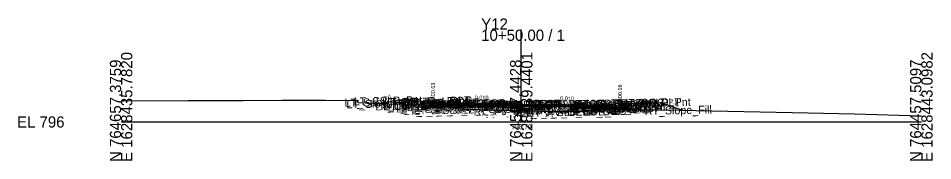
# Model space of a CAD drawing. Extents: x -26 to 203, y -10 to 3521.
# Drawn here: x -25.7 to 202.8, y 990.3 to 1025.9 of the extents above; entities that cross this region are included whole.
import ezdxf

# ---------------------------------------------------------------- set-up
doc = ezdxf.new("R2010")
doc.units = 0
for name, color, linetype in [('Default', 7, 'Continuous'), ('Exist CMT Pavement', 7, 'Continuous'), ('Exist Cross Section Cell', 7, 'Continuous'), ('Exist XS Center Line Elevation Label', 7, 'Continuous'), ('Exist XS Ground Line', 7, 'Continuous'), ('Prop CMT Conc Surface', 7, 'Continuous'), ('Prop CMT Concrete Structures', 7, 'Continuous'), ('Prop CMT Pvmt Course 1', 7, 'Continuous'), ('Prop CMT Pvmt Course 1 CG', 7, 'Continuous'), ('Prop CMT Pvmt Course 1 Wedge', 7, 'Continuous'), ('Prop CMT Pvmt Course 2', 7, 'Continuous'), ('Prop CMT Pvmt Course 2 Wedge', 7, 'Continuous'), ('Prop CMT Pvmt Course 3', 7, 'Continuous'), ('Prop CMT Pvmt Course 3 Wedge', 7, 'Continuous'), ('Prop CMT Pvmt Surface', 7, 'Continuous'), ('Prop CMT Pvmt Wedge Surface 1', 7, 'Continuous'), ('Prop CMT Pvmt Wedge Surface 2', 7, 'Continuous'), ('Prop CMT Pvmt Wedge Surface 3', 7, 'Continuous'), ('Prop CMT Slope Grass', 7, 'Continuous'), ('Prop CMT Subgrade Earthwork', 7, 'Continuous'), ('Prop XS Hydro Elevations', 7, 'Continuous'), ('Prop XS SE Text', 7, 'Continuous'), ('Prop XS Side Slope Text', 7, 'Continuous'), ('Scratch_Level_0', 7, 'Continuous')]:
    doc.layers.add(name, color=color, linetype=linetype)

msp = doc.modelspace()

# ---------------------------------------------------------------- linework, layer by layer
at = {"layer": 'Exist CMT Pavement'}
for points in [[(100, 1002.79), (97.69, 1002.83), (85.63, 1003.08)], [(85.63, 1003.08), (85.63, 1003.08)], [(100, 1002.79), (113.86, 1002.55)], [(113.86, 1002.55), (113.86, 1002.55)]]:
    msp.add_lwpolyline(points, dxfattribs=at)
at = {"layer": 'Exist Cross Section Cell'}
for p, q in [((100, 1000), (100, 1023.09)), ((0, 1000), (100, 1000)), ((100, 1000), (200, 1000))]:
    msp.add_line(p, q, dxfattribs=at)
at = {"layer": 'Exist XS Ground Line'}
msp.add_lwpolyline([(0, 1005.28), (0.59, 1005.28), (16.74, 1005.4), (30.48, 1005.4), (40.27, 1005.47), (51.02, 1005.49), (58.8, 1005.41), (59.21, 1004.91), (66.95, 1004.55), (70.07, 1004.41), (74.01, 1004.03), (80.92, 1003.88), (85.63, 1003.08), (97.69, 1002.83), (100, 1002.79), (113.86, 1002.55), (116.68, 1002.85), (119.9, 1003.29), (122.33, 1003.21), (139.66, 1002.98), (171.73, 1002.25), (183.27, 1002.03), (200, 1001.5)], dxfattribs=at)
at = {"layer": 'Prop CMT Conc Surface'}
for points in [[(77.97, 1004.63), (77.97, 1005.13), (77.47, 1005.13)], [(79.97, 1004.69), (77.97, 1004.63)], [(122.69, 1004.26), (124.69, 1004.16)], [(124.69, 1004.16), (124.69, 1004.66), (125.19, 1004.66)]]:
    msp.add_lwpolyline(points, dxfattribs=at)
at = {"layer": 'Prop CMT Concrete Structures'}
for points in [[(79.97, 1004.69), (77.97, 1004.63), (77.97, 1005.13), (77.47, 1005.13)], [(77.47, 1005.13), (77.47, 1004.13), (79.97, 1004.11)], [(79.97, 1004.11), (79.97, 1004.69)], [(122.69, 1004.26), (124.69, 1004.16), (124.69, 1004.66), (125.19, 1004.66)], [(125.19, 1004.66), (125.19, 1003.66), (122.69, 1003.68)], [(122.69, 1003.68), (122.69, 1004.26)]]:
    msp.add_lwpolyline(points, dxfattribs=at)
at = {"layer": 'Prop CMT Pvmt Course 1'}
for points in [[(100, 1004.49), (79.97, 1004.69)], [(79.97, 1004.69), (79.97, 1004.44)], [(79.97, 1004.44), (85.63, 1004.39)], [(85.63, 1004.39), (85.63, 1004.51)], [(85.63, 1004.51), (100, 1004.37)], [(100, 1004.24), (100, 1004.49)], [(100, 1004.49), (122.69, 1004.26)], [(100, 1004.24), (100, 1004.49)], [(100, 1004.37), (100, 1004.24), (100, 1004.24)], [(113.86, 1004.23), (100, 1004.37)], [(100, 1004.37), (100, 1004.24), (100, 1004.24)], [(113.86, 1004.1), (113.86, 1004.23)], [(122.69, 1004.01), (113.86, 1004.1)], [(122.69, 1004.26), (122.69, 1004.01)]]:
    msp.add_lwpolyline(points, dxfattribs=at)
at = {"layer": 'Prop CMT Pvmt Course 1 CG'}
for points in [[(79.97, 1004.11), (76.97, 1004.14), (76.64, 1003.81)], [(76.64, 1003.81), (79.97, 1003.78)], [(79.97, 1003.78), (79.97, 1004.11)], [(122.69, 1003.68), (125.69, 1003.65), (126.03, 1003.31)], [(122.69, 1003.35), (122.69, 1003.68)], [(126.03, 1003.31), (122.69, 1003.35)]]:
    msp.add_lwpolyline(points, dxfattribs=at)
at = {"layer": 'Prop CMT Pvmt Course 1 Wedge'}
for points in [[(85.63, 1004.51), (85.63, 1004.51)], [(85.63, 1004.51), (97.69, 1004.39), (100, 1004.37)], [(85.63, 1004.39), (85.63, 1004.51)], [(100, 1004.24), (97.69, 1004.26), (85.63, 1004.39)], [(85.63, 1004.39), (85.63, 1004.39)], [(100, 1004.37), (100, 1004.24)], [(100, 1004.37), (113.86, 1004.23)], [(100, 1004.24), (100, 1004.37)], [(113.86, 1004.1), (100, 1004.24)], [(113.86, 1004.23), (113.86, 1004.1), (113.86, 1004.1)]]:
    msp.add_lwpolyline(points, dxfattribs=at)
at = {"layer": 'Prop CMT Pvmt Course 2'}
for points in [[(85.63, 1004.39), (79.97, 1004.44)], [(79.97, 1004.44), (79.97, 1004.11)], [(79.97, 1004.11), (85.63, 1004.05)], [(85.63, 1004.05), (85.63, 1004.39)], [(113.86, 1003.77), (113.86, 1004.1)], [(113.86, 1004.1), (122.69, 1004.01)], [(122.69, 1003.68), (113.86, 1003.77)], [(122.69, 1004.01), (122.69, 1003.68)]]:
    msp.add_lwpolyline(points, dxfattribs=at)
at = {"layer": 'Prop CMT Pvmt Course 2 Wedge'}
for points in [[(85.63, 1004.39), (85.63, 1004.39)], [(85.63, 1004.39), (97.69, 1004.26), (100, 1004.24)], [(85.63, 1004.05), (85.63, 1004.39)], [(100, 1003.91), (97.69, 1003.93), (85.63, 1004.05)], [(85.63, 1004.05), (85.63, 1004.05)], [(100, 1004.24), (100, 1003.91)], [(100, 1004.24), (113.86, 1004.1)], [(100, 1003.91), (100, 1004.24)], [(113.86, 1003.77), (100, 1003.91)], [(113.86, 1004.1), (113.86, 1003.77), (113.86, 1003.77)]]:
    msp.add_lwpolyline(points, dxfattribs=at)
at = {"layer": 'Prop CMT Pvmt Course 3'}
for points in [[(85.63, 1004.05), (79.97, 1004.11)], [(79.97, 1004.11), (79.97, 1003.78)], [(79.97, 1003.78), (85.63, 1003.72)], [(85.63, 1003.72), (85.63, 1004.05)], [(113.86, 1003.77), (122.69, 1003.68)], [(113.86, 1003.44), (113.86, 1003.77)], [(122.69, 1003.35), (113.86, 1003.44)], [(122.69, 1003.68), (122.69, 1003.35)]]:
    msp.add_lwpolyline(points, dxfattribs=at)
at = {"layer": 'Prop CMT Pvmt Course 3 Wedge'}
for points in [[(85.63, 1004.05), (85.63, 1004.05)], [(85.63, 1004.05), (97.69, 1003.93), (100, 1003.91)], [(85.63, 1003.08), (85.63, 1004.05)], [(100, 1003.91), (100, 1002.79)], [(100, 1003.91), (113.86, 1003.77)], [(100, 1002.79), (100, 1003.91)], [(113.86, 1003.77), (113.86, 1002.55), (113.86, 1002.55)], [(100, 1002.79), (97.69, 1002.83), (85.63, 1003.08)], [(85.63, 1003.08), (85.63, 1003.08)], [(113.86, 1002.55), (100, 1002.79)]]:
    msp.add_lwpolyline(points, dxfattribs=at)
at = {"layer": 'Prop CMT Pvmt Surface'}
for points in [[(100, 1004.49), (79.97, 1004.69)], [(100, 1004.49), (122.69, 1004.26)]]:
    msp.add_lwpolyline(points, dxfattribs=at)
at = {"layer": 'Prop CMT Pvmt Wedge Surface 1'}
for points in [[(79.97, 1004.44), (79.97, 1004.69)], [(85.63, 1004.39), (79.97, 1004.44)], [(100, 1004.37), (85.63, 1004.51)], [(85.63, 1004.51), (85.63, 1004.39)], [(100, 1004.37), (113.86, 1004.23)], [(113.86, 1004.23), (113.86, 1004.1)], [(113.86, 1004.1), (122.69, 1004.01)], [(122.69, 1004.01), (122.69, 1004.26)]]:
    msp.add_lwpolyline(points, dxfattribs=at)
at = {"layer": 'Prop CMT Pvmt Wedge Surface 2'}
for points in [[(79.97, 1004.44), (79.97, 1004.69)], [(100, 1004.24), (79.97, 1004.44)], [(100, 1004.24), (122.69, 1004.01)], [(122.69, 1004.01), (122.69, 1004.26)]]:
    msp.add_lwpolyline(points, dxfattribs=at)
at = {"layer": 'Prop CMT Pvmt Wedge Surface 3'}
for points in [[(79.97, 1004.11), (79.97, 1004.69)], [(100, 1003.91), (79.97, 1004.11)], [(100, 1003.91), (122.69, 1003.68)], [(122.69, 1003.68), (122.69, 1004.26)]]:
    msp.add_lwpolyline(points, dxfattribs=at)
at = {"layer": 'Prop CMT Slope Grass'}
for points in [[(77.47, 1005.13), (67.97, 1005.32), (65.82, 1004.6)], [(125.19, 1004.66), (134.69, 1004.85), (140.37, 1002.96)]]:
    msp.add_lwpolyline(points, dxfattribs=at)
at = {"layer": 'Prop CMT Subgrade Earthwork'}
for points in [[(79.97, 1003.78), (76.64, 1003.81), (75.28, 1005.18)], [(85.63, 1003.72), (79.97, 1003.78)], [(85.63, 1003.72), (85.65, 1003.08)], [(113.86, 1003.44), (113.84, 1002.55)], [(113.86, 1003.44), (122.69, 1003.35)], [(122.69, 1003.35), (126.03, 1003.31), (127.42, 1004.71)]]:
    msp.add_lwpolyline(points, dxfattribs=at)

# ---------------------------------------------------------------- texts
at = {"layer": 'Default'}
msp.add_text('-', height=0.0001, dxfattribs=at).set_placement((0, 1000))
at = {"layer": 'Exist Cross Section Cell'}
for s, p in [('Y12', (90, 1023.09)), ('10+50.00 / 1', (90, 1020.29)), ('EL 796', (-26, 998.6))]:
    msp.add_text(s, height=2.8, dxfattribs=at).set_placement(p)
for s, p in [('E 1628435.7820', (2.8, 990)), ('E 1628439.4401', (102.8, 990)), ('E 1628443.0982', (202.8, 990)), ('N 764657.3759', (0, 990)), ('N 764557.4428', (100, 990)), ('N 764457.5097', (200, 990))]:
    msp.add_text(s, height=2.8, rotation=90, dxfattribs=at).set_placement(p)
at = {"layer": 'Exist XS Center Line Elevation Label'}
msp.add_text('798.79', height=1.2, dxfattribs=at).set_placement((97.54, 998.19))
at = {"layer": 'Prop XS Hydro Elevations'}
for s, p in [('800.63', (78.47, 1005.63)), ('800.16', (125.19, 1005.16))]:
    msp.add_text(s, height=1, rotation=90, dxfattribs=at).set_placement(p)
at = {"layer": 'Prop XS SE Text'}
for p in [(88.37, 1005.61), (109.73, 1005.39)]:
    msp.add_text('0.010', height=1, rotation=359.4271, dxfattribs=at).set_placement(p)
at = {"layer": 'Prop XS Side Slope Text'}
for rotation, p in [(18.4332, (65.91, 1005.42)), (341.5668, (137.02, 1004.87))]:
    msp.add_text('3:1', height=1, rotation=rotation, dxfattribs=at).set_placement(p)
at = {"layer": 'Scratch_Level_0'}
for s, p in [('LT_Sub_Trench_Out_DLT', (55.87, 1003.79)), ('LT_Slope_Fill', (56.36, 1003.41)), ('LT_CSLP_Pnt', (58.17, 1004.13)), ('LT_CG_Top_Face', (65.25, 1003.88)), ('LT_CG_Top_BOC', (65.78, 1003.9)), ('LT_CG_Top_Gut', (66.23, 1003.4)), ('LT_PV2_OEOT', (70.17, 1003.25)), ('LT_PV1_OEOT', (70.74, 1003.51)), ('LT_PV2_OEEOP', (74.96, 1003.17)), ('LT_PV1_OEEOP', (75.53, 1003.31)), ('RT_PV1_IEEOP', (90.49, 1003.18)), ('LT_PV1_IEEOP', (90.54, 1003.18)), ('PV1_PGL', (94.49, 1003.38)), ('RT_Sub_Trench_Out_DLT', (107.97, 1003.32)), ('RT_CG_Top_Face', (111.93, 1003.41)), ('RT_CG_Top_BOC', (113.45, 1003.43)), ('RT_CSLP_Pnt', (124.84, 1003.66)), ('LT_CG1_Shelf_Out', (63.55, 1002.87)), ('LT_CG_Bot_BOC', (65.81, 1002.9)), ('LT_Sub_OEOP', (66.78, 1002.61)), ('LT_CG_Bot_IE', (69.91, 1002.91)), ('LT_Sub_OEOT', (70.07, 1002.58)), ('LT_PV3_OEOT', (70.17, 1002.91)), ('LT_PV_Sub_Tie_Out', (70.61, 1001.77)), ('LT_PV_OEEOP_EG', (73.2, 1001.83)), ('LT_Sub_OEEOP', (74.87, 1002.5)), ('LT_PV3_OEEOP', (74.96, 1002.84)), ('RT_PV_IEEOP_EG', (88.16, 1001.55)), ('LT_PV_IEEOP_EG', (88.21, 1001.55)), ('RT_PV2_IEEOP', (89.93, 1003.04)), ('RT_PV3_IEEOP', (89.93, 1002.71)), ('LT_PV2_IEEOP', (89.97, 1003.04)), ('LT_PV3_IEEOP', (89.97, 1002.71)), ('PV2_PGL', (93.93, 1003.12)), ('RT_PV_Sub_Tie_Out', (98.76, 1001.25)), ('RT_PV_OEEOP_EG', (101.37, 1001.3)), ('RT_Sub_OEEOP', (103.04, 1002.22)), ('RT_PV2_OEEOP', (103.14, 1002.89)), ('RT_PV3_OEEOP', (103.14, 1002.56)), ('RT_PV1_OEEOP', (103.7, 1003.02)), ('RT_CG1_Shelf_Out', (112.22, 1002.38)), ('RT_CG_Bot_IE', (112.58, 1002.48)), ('RT_Sub_OEOT', (112.74, 1002.15)), ('RT_PV2_OEOT', (112.84, 1002.82)), ('RT_PV3_OEOT', (112.84, 1002.48)), ('RT_CG_Top_Gut', (112.9, 1002.93)), ('RT_PV1_OEOT', (113.41, 1003.08)), ('RT_CG_Bot_BOC', (113.48, 1002.42)), ('RT_Sub_OEOP', (116.11, 1002.12)), ('RT_Slope_Fill', (130.87, 1001.77))]:
    msp.add_text(s, height=2, rotation=1.1458, dxfattribs=at).set_placement(p)

doc.saveas('drawing.dxf')
